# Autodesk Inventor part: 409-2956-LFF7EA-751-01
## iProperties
Created: 2010-06
Part Number: 409-2956-LFF7EA-751-01
Material: Sch40 CS PIPE SEAMLESS
Description: PIPE
Document SubType Name: Modeling
Designer: S. Boerckel
Engineer: Steve Boerckel
Mass: 958.943 g
Surface Area: 638.46 cm^2
Volume: 122.158 cm^3
Density: 7.85 g/cm^3
Cost Center: 2"
SMR: =<COST CENTER> - <Material>
Length: 6.938 in
Title: 2"
Author: S. Boerckel
Revision Number: B
Subject: DEMIN WATER FORWARDING PUMP SKID-7EA
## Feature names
1. Extrusion1
